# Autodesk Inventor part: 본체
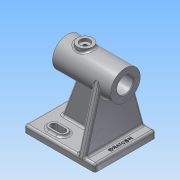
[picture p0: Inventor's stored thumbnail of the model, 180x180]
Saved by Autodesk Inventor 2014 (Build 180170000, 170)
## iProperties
Created: 2019-10
Part Number: 본체
Material: 알루미늄 6061
Document SubType Name: Modeling
Designer: NET
Density: 2.71 g/cm^3
Appearance: 알루미늄 - 평지
Mass: 588.619 g
Surface Area: 540.35 cm^2
Volume: 217.202 cm^3
Author: NET
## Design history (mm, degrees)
sketch "스케치1"
  geometry: L1 (-41, 0)-(41, 0); L2 (-41, 14.5)-(21, 14.5); L3 (21, 14.5)-(21, 11.5); L4 (21, 11.5)-(41, 11.5); L5 (41, 11.5)-(41, 21); L6 (41, 21)-(-41, 21); L7 (-41, 21)-(-41, 14.5); 2 further points
  constraints: 14 end point, 5 parallel, 2 point on line, 1 coincident, 1 horizontal, 1 midpoint, 1 perpendicular
  dimensions: "d0" = 82 distance of L1.start L1.end; "d1" = 23 diameter of L4 L1; "d2" = 29 diameter of L2 L1; "d3" = 42 diameter of L6 L1; "d4" = 62 distance of L2.start L2.end
revolve "회전1" sketch "스케치1" stored, may be unused: angle "d5" = 90 deg
node "작업 평면1"
sketch "스케치2"
  geometry: L1 (41, -21)-(41, 21) reference; L2 (-59, 43)-(41, 43); L3 (41, 43)-(41, -43); L4 (41, -43)-(-59, -43); L5 (-59, -43)-(-59, 43); 2 further points
  constraints: 8 end point, 2 parallel, 1 collinear, 1 horizontal, 1 horizontal alignment, 1 midpoint, 1 perpendicular
  dimensions: "d7" = 86 distance of L2.end L3.end; "d8" = 100 distance of L2.start L2.end
extrude "돌출1" join sketch "스케치2" distance "d9" = 10; taper "d10" = 0 deg
node "작업 평면2"
fillet "모깎기6" dims "d36" = 3
fillet "모깎기7" dims "d37" = 3
sketch "스케치4"
  geometry: L1 (-59, 43)-(-59, -43) reference; L2 (-33, 27)-(-21, 27); L3 (-33, 20)-(-21, 20); L4 (-21, 34)-(-33, 34); A1 r 7 centre (-33, 27) between (-33, 34) and (-33, 20); A2 r 7 centre (-21, 27) between (-21, 20) and (-21, 34); 2 further points
  constraints: 8 end point, 4 point on circle, 4 tangent, 2 centre point, 1 horizontal, 1 midpoint, 1 parallel
  dimensions: "d14" = 26 distance from line of L1 L2.start; "d15" = 12 distance of L2.start L2.end; "d16" = 7 radius of A1; "d17" = 27 distance from line of point (0, 0) L2
extrude "돌출3" join sketch "스케치4" distance "d18" = 3; taper "d19" = 0 deg
sketch "스케치5"
  geometry: L1 (-33, 20)-(-21, 20) reference; L2 (-33, 27)-(-21, 27); L3 (-33, 22.5)-(-21, 22.5); L4 (-21, 31.5)-(-33, 31.5); A1 r 7 centre (-21, 27) between (-21, 20) and (-21, 34) reference; A2 r 7 centre (-33, 27) between (-33, 34) and (-33, 20) reference; A3 r 4.5 centre (-33, 27) between (-33, 31.5) and (-33, 22.5); A4 r 4.5 centre (-21, 27) between (-21, 22.5) and (-21, 31.5); 2 further points
  constraints: 8 end point, 4 point on circle, 4 tangent, 2 centre point, 2 parallel, 1 midpoint
  dimensions: "d20" = 4.5 radius of A4
extrude "돌출4" cut sketch "스케치5" stored distance "d21" = 3; taper "d22" = 0 deg
fillet "모깎기1" dims "d23" = 3
sketch "스케치7"
  geometry: L1 (76, -40)-(76, 40) reference; L2 (79, 43)-(86, 43) reference; L3 (86, 43)-(86, -43) reference; L4 (86, -43)-(79, -43) reference; L5 (78.217, 42.896)-(-5.48, 20.272); L6 (78.217, -42.896)-(-5.48, -20.272); C1 r 11.5 at (0, 0) reference; A1 r 3 centre (79, 40) between (79, 43) and (76, 40) reference; A2 r 3 centre (79, -40) between (76, -40) and (79, -43) reference; A3 r 21 centre (0, 0) between (-5.48, 20.272) and (-5.48, -20.272) reference; 1 further point
  constraints: 4 end point, 4 point on circle, 4 tangent
extrude "돌출5" join sketch "스케치7" distance "d38" = 10; taper "d39" = 0 deg
fillet "모깎기8" dims "d40" = 3
fillet "모깎기9" dims "d41" = 3
sketch "스케치8"
  geometry: L1 (41, 21)-(41, 14.5) reference; L2 (41, 14.5)-(-21, 14.5) reference; L3 (-21, 14.5)-(-21, 11.5) reference; L4 (-21, 11.5)-(-41, 11.5) reference; L5 (-41, 11.5)-(-41, 21) reference; L6 (-41, 21)-(41, 21) reference; L7 (41, -14.5)-(41, -21) reference; L8 (41, -21)-(-16, -21) reference; L9 (-16, -21)-(-16, -76) reference; L10 (-16, -76)-(56, -76) reference; L11 (59, -79)-(59, -86) reference; L12 (59, -86)-(-41, -86) reference; L13 (-41, -86)-(-41, -79) reference; L14 (-38, -76)-(-29, -76) reference; L15 (-26, -73)-(-26, -21) reference; L16 (-26, -21)-(-41, -21) reference; L17 (-41, -21)-(-41, -11.5) reference; L18 (-41, -11.5)-(-21, -11.5) reference; L19 (-21, -11.5)-(-21, -14.5) reference; L20 (-21, -14.5)-(41, -14.5) reference; L21 (44, -76)-(24.357, -22.031); A1 r 3 centre (56, -79) between (59, -79) and (56, -76) reference; A2 r 3 centre (-38, -79) between (-38, -76) and (-41, -79) reference; A3 r 3 centre (-29, -73) between (-29, -76) and (-26, -73) reference; 1 further point
  constraints: 2 end point, 1 point on line
  dimensions: "d42" = 15 distance from line of L11 L21.start; "d43" = 70 deg angle of L10 L21
feature "리브2" sketch "스케치8" dims "d44" = 1, "d45" = 10, "d46" = 0, "d47" = 0, "d48" = 1, "d49" = 1
fillet "모깎기10" dims "d50" = 3
fillet "모깎기11" dims "d51" = 3
sketch "스케치9"
  geometry: C1 r 11.5 at (0, 0) reference; 1 further point
  constraints: 1 vertical alignment
  dimensions: "d52" = 18 distance of C1.centre point (0, 18)
hole "구멍1" sketch "스케치9" at (0, 18) diameter "d53" = 2.459; stored, may be unused: countersink angle "d57" = 90 deg, drill point angle "d59" = 118 deg; dims "d54" = 8, "d55" = 4, "d56" = 2, "d58" = 10
chamfer "모따기1" distance "d63" = 1; stored, may be unused: second distance "d64" = 2, angle "d65" = 45 deg
chamfer "모따기2" distance "d66" = 1; stored, may be unused: second distance "d67" = 2, angle "d68" = 45 deg
node "작업 평면3"
sketch "스케치10"
  geometry: L1 (-41, -21)-(-41, 21) reference; L2 (41, -21)-(41, 21) reference; C1 r 11 at (-16, 0); 2 further points
  constraints: 1 centre point, 1 horizontal alignment, 1 midpoint
  dimensions: "d70" = 22 diameter of C1; "d71" = 25 distance from line of C1.centre L1
extrude "돌출6" join sketch "스케치10" stored distance "d72" = 10; taper "d73" = 0 deg
sketch "스케치11"
  geometry: C1 r 11 at (0, 0) reference; C2 r 7 at (0, 0); 1 further point
  constraints: 1 centre point, 1 coincident
  dimensions: "d74" = 14 diameter of C2
extrude "돌출7" cut sketch "스케치11" distance "d75" = 4; taper "d76" = 0 deg
sketch "스케치12"
  geometry: C1 r 7 at (0, 0) reference; 2 further points
  constraints: 1 coincident
hole "구멍2" sketch "스케치12" at (0, 0) diameter "d77" = 4.917; stored, may be unused: countersink angle "d81" = 90 deg, drill point angle "d83" = 118 deg; dims "d78" = 8, "d79" = 4, "d80" = 2, "d82" = 10
fillet "모깎기12" dims "d84" = 3
sketch "스케치13"
  geometry: L1 (41, -40)-(41, 40) reference; 2 further points
  constraints: 1 horizontal alignment, 1 other
  dimensions: "d85" = 7 distance from line of point (34, 0) L1
feature "엠보싱1" sketch "스케치13" dims "d0" = 82, "d1" = 23, "d2" = 29, "d3" = 42, "d4" = 62, "d86" = 0.5, "d87" = 0
node "솔리드1"
mirror "대칭1"
pattern_circular "원형 패턴1" dims angle "d61" = 360 deg
mirror "대칭2"
node "절단 모서리 투영3"
node "절단 모서리 투영4"
other parameters: "d6" = -86, "d11" = -15, "d69" = 24
